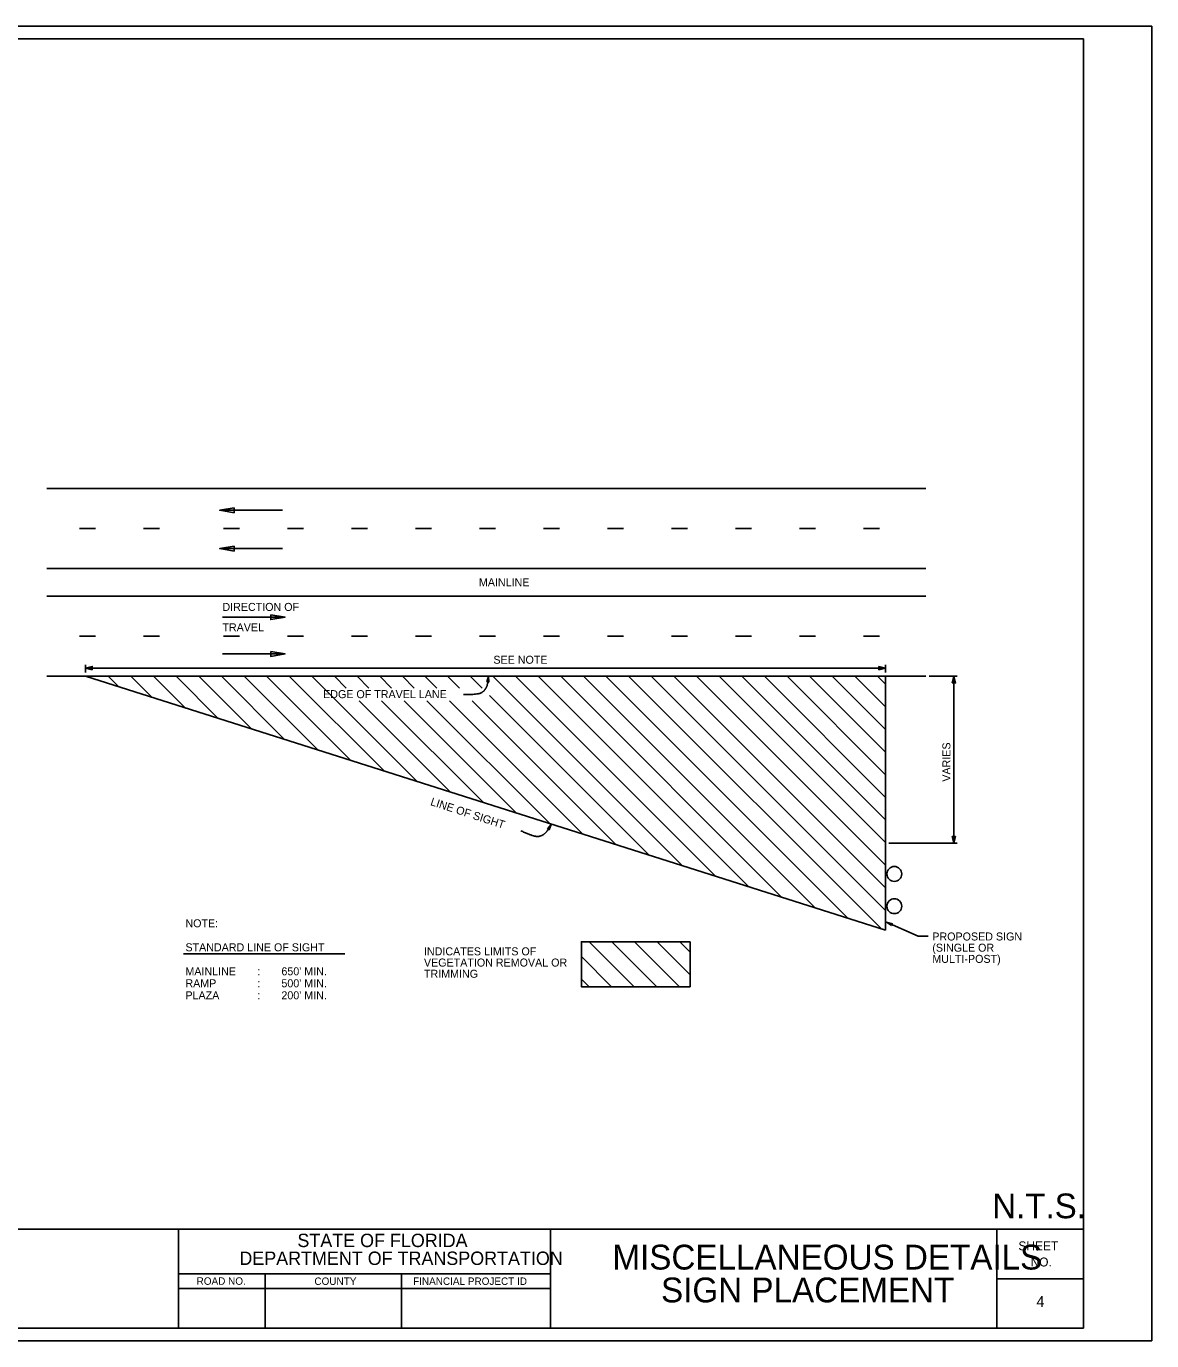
# Model space of a CAD drawing. Extents: x 17890189 to 17891344, y 17896595 to 17897992.
# Drawn here: x 17890708 to 17891344, y 17896595 to 17897337 of the extents above; entities that cross this region are included whole.
import ezdxf

# ---------------------------------------------------------------- set-up
doc = ezdxf.new("R2010")
doc.units = 0
for name, color, linetype in [('Default', 7, 'Continuous'), ('DimLines_dp', 7, 'Continuous'), ('LeaderLine_dp', 7, 'Continuous'), ('PlotBorder_dp', 7, 'Continuous'), ('ScratchEle_dp', 7, 'Continuous'), ('SheetBorder_dp', 7, 'Continuous'), ('SheetLines_dp', 7, 'Continuous'), ('TextLabel', 7, 'Continuous'), ('TextMisc', 7, 'Continuous'), ('TextShtNo', 7, 'Continuous')]:
    doc.layers.add(name, color=color, linetype=linetype)

msp = doc.modelspace()

# ---------------------------------------------------------------- linework, layer by layer
at = {"layer": 'Default'}
for p, q in [((17890719.8, 17897075.52), (17891216.02, 17897075.52)), ((17890738.25, 17897052.94), (17890747.28, 17897052.94)), ((17890774.38, 17897052.94), (17890783.41, 17897052.94)), ((17890819.54, 17897052.94), (17890828.57, 17897052.94)), ((17890855.67, 17897052.94), (17890864.7, 17897052.94)), ((17890891.8, 17897052.94), (17890900.83, 17897052.94)), ((17890927.93, 17897052.94), (17890936.96, 17897052.94)), ((17890964.06, 17897052.94), (17890973.09, 17897052.94)), ((17891000.19, 17897052.94), (17891009.22, 17897052.94)), ((17891036.32, 17897052.94), (17891045.35, 17897052.94)), ((17891072.44, 17897052.94), (17891081.48, 17897052.94)), ((17891108.57, 17897052.94), (17891117.61, 17897052.94)), ((17891144.7, 17897052.94), (17891153.73, 17897052.94)), ((17891180.83, 17897052.94), (17891189.86, 17897052.94)), ((17890719.8, 17897030.36), (17891216.02, 17897030.36)), ((17890719.8, 17897014.78), (17891216.02, 17897014.78)), ((17890738.25, 17896992.2), (17890747.28, 17896992.2)), ((17890774.38, 17896992.2), (17890783.41, 17896992.2)), ((17890819.54, 17896992.2), (17890828.57, 17896992.2)), ((17890855.67, 17896992.2), (17890864.7, 17896992.2)), ((17890891.8, 17896992.2), (17890900.83, 17896992.2)), ((17890927.93, 17896992.2), (17890936.96, 17896992.2)), ((17890964.06, 17896992.2), (17890973.09, 17896992.2)), ((17891000.19, 17896992.2), (17891009.22, 17896992.2)), ((17891036.32, 17896992.2), (17891045.35, 17896992.2)), ((17891072.44, 17896992.2), (17891081.48, 17896992.2)), ((17891108.57, 17896992.2), (17891117.61, 17896992.2)), ((17891144.7, 17896992.2), (17891153.73, 17896992.2)), ((17891180.83, 17896992.2), (17891189.86, 17896992.2)), ((17890741.72, 17896971.62), (17890741.72, 17896976.11)), ((17891193.33, 17896974.23), (17890741.72, 17896974.23)), ((17891193.33, 17896971.62), (17891193.33, 17896976.11)), ((17890719.8, 17896969.62), (17891216.02, 17896969.62)), ((17891193.33, 17896826.19), (17890741.72, 17896969.62)), ((17890741.75, 17896969.61), (17890741.74, 17896969.62)), ((17890760.47, 17896963.66), (17890754.51, 17896969.62)), ((17890779.19, 17896957.72), (17890767.29, 17896969.62)), ((17890797.9, 17896951.78), (17890780.06, 17896969.62)), ((17890816.62, 17896945.83), (17890792.84, 17896969.62)), ((17890835.34, 17896939.89), (17890805.61, 17896969.62)), ((17890854.06, 17896933.94), (17890818.38, 17896969.62)), ((17890872.78, 17896928), (17890831.16, 17896969.62)), ((17890891.49, 17896922.05), (17890843.93, 17896969.62)), ((17890910.21, 17896916.11), (17890856.7, 17896969.62)), ((17890928.93, 17896910.16), (17890869.48, 17896969.62)), ((17890888.92, 17896962.95), (17890882.25, 17896969.62)), ((17890901.69, 17896962.95), (17890895.02, 17896969.62)), ((17890914.47, 17896962.95), (17890907.8, 17896969.62)), ((17890927.24, 17896962.95), (17890920.57, 17896969.62)), ((17890940.01, 17896962.95), (17890933.34, 17896969.62)), ((17890952.79, 17896962.95), (17890946.12, 17896969.62)), ((17890965.56, 17896962.95), (17890958.89, 17896969.62)), ((17891078.68, 17896862.61), (17890971.66, 17896969.62)), ((17891097.4, 17896856.66), (17890984.44, 17896969.62)), ((17891116.11, 17896850.72), (17890997.21, 17896969.62)), ((17891134.83, 17896844.77), (17891009.98, 17896969.62)), ((17891153.55, 17896838.83), (17891022.76, 17896969.62)), ((17891172.27, 17896832.88), (17891035.53, 17896969.62)), ((17891190.99, 17896826.94), (17891048.3, 17896969.62)), ((17891193.33, 17896837.36), (17891061.08, 17896969.62)), ((17891193.33, 17896850.14), (17891073.85, 17896969.62)), ((17891193.33, 17896862.91), (17891086.63, 17896969.62)), ((17891193.33, 17896875.68), (17891099.4, 17896969.62)), ((17891193.33, 17896888.46), (17891112.17, 17896969.62)), ((17891193.33, 17896901.23), (17891124.95, 17896969.62)), ((17891193.33, 17896914), (17891137.72, 17896969.62)), ((17891193.33, 17896926.78), (17891150.49, 17896969.62)), ((17891193.33, 17896939.55), (17891163.27, 17896969.62)), ((17891193.33, 17896952.32), (17891176.04, 17896969.62)), ((17891193.33, 17896965.1), (17891188.81, 17896969.62)), ((17891193.33, 17896875.36), (17891193.33, 17896969.62)), ((17891217.91, 17896969.62), (17891233.8, 17896969.62)), ((17891059.96, 17896868.55), (17890969.73, 17896958.78)), ((17890947.65, 17896904.22), (17890896.09, 17896955.78)), ((17890966.37, 17896898.27), (17890908.86, 17896955.78)), ((17890985.09, 17896892.33), (17890921.64, 17896955.78)), ((17891003.8, 17896886.38), (17890934.41, 17896955.78)), ((17891022.52, 17896880.44), (17890947.18, 17896955.78)), ((17891041.24, 17896874.49), (17890959.96, 17896955.78)), ((17891193.33, 17896875.36), (17891193.33, 17896826.19)), ((17891051.51, 17896794.31), (17891026.09, 17896819.73)), ((17891064.28, 17896794.31), (17891038.86, 17896819.73)), ((17891077.06, 17896794.31), (17891051.64, 17896819.73)), ((17891083.02, 17896801.12), (17891064.41, 17896819.73)), ((17891083.02, 17896813.9), (17891077.18, 17896819.73)), ((17891038.73, 17896794.31), (17891021.68, 17896811.37)), ((17891025.96, 17896794.31), (17891021.68, 17896798.6))]:
    msp.add_line(p, q, dxfattribs=at)
for points in [[(17890745.48, 17896973.29), (17890741.72, 17896974.23), (17890745.48, 17896975.17)], [(17891189.57, 17896975.17), (17891193.33, 17896974.23), (17891189.57, 17896973.29)], [(17891002.46, 17896883.51), (17891003.38, 17896882.94), (17891004.62, 17896886)], [(17891083.02, 17896819.73), (17891021.68, 17896819.73), (17891021.68, 17896794.31), (17891083.02, 17896794.31)]]:
    msp.add_lwpolyline(points, close=True, dxfattribs=at)
for centre in [(17891198.32, 17896857.99), (17891198.32, 17896839.79)]:
    msp.add_circle(centre, 4.21, dxfattribs=at)
msp.add_open_spline([(17890987.39, 17896882.36), (17890995.04, 17896878.92), (17890999.26, 17896879.34), (17891002.68, 17896882.29), (17891004.52, 17896885.88)], degree=2, dxfattribs=at)
at = {"layer": 'DimLines_dp'}
msp.add_line((17891231.91, 17896969.62), (17891231.91, 17896875.36), dxfattribs=at)
at = {"layer": 'LeaderLine_dp'}
for p, q in [((17890852.86, 17897063.29), (17890817.45, 17897063.29)), ((17890852.86, 17897041.65), (17890817.45, 17897041.65)), ((17890818.97, 17897002.96), (17890854.38, 17897002.96)), ((17890818.97, 17896982.17), (17890854.38, 17896982.17)), ((17891195.22, 17896875.36), (17891233.8, 17896875.36)), ((17891211.78, 17896822.83), (17891193.93, 17896830.71)), ((17891217.5, 17896822.83), (17891211.78, 17896822.83))]:
    msp.add_line(p, q, dxfattribs=at)
for points in [[(17890825.58, 17897064.64), (17890825.58, 17897061.93), (17890817.45, 17897063.29)], [(17890825.58, 17897043.01), (17890825.58, 17897040.3), (17890817.45, 17897041.65)], [(17890846.25, 17897004.32), (17890846.25, 17897001.61), (17890854.38, 17897002.96)], [(17890846.25, 17896983.52), (17890846.25, 17896980.81), (17890854.38, 17896982.17)], [(17890968.27, 17896966.47), (17890969.34, 17896966.33), (17890969.22, 17896969.62)], [(17891230.97, 17896965.86), (17891231.91, 17896969.62), (17891232.86, 17896965.86)], [(17891232.86, 17896879.12), (17891231.91, 17896875.36), (17891230.97, 17896879.12)], [(17891196.68, 17896828.9), (17891197.12, 17896829.89), (17891193.93, 17896830.71)]]:
    msp.add_lwpolyline(points, close=True, dxfattribs=at)
msp.add_open_spline([(17890955, 17896959.24), (17890963.38, 17896959.24), (17890967.06, 17896961.36), (17890968.97, 17896965.45), (17890969.18, 17896969.47)], degree=2, dxfattribs=at)
at = {"layer": 'PlotBorder_dp'}
msp.add_lwpolyline([(17890188.62, 17896594.5), (17891343.62, 17896594.5), (17891343.62, 17897336.5), (17890188.62, 17897336.5)], close=True, dxfattribs=at)
at = {"layer": 'ScratchEle_dp'}
msp.add_line((17890796.99, 17896812.99), (17890888.02, 17896812.99), dxfattribs=at)
at = {"layer": 'SheetBorder_dp'}
for p, q in [((17890227.12, 17897329.5), (17891305.12, 17897329.5)), ((17891305.12, 17897329.5), (17891305.12, 17896601.5)), ((17890227.12, 17896657.5), (17891305.12, 17896657.5)), ((17890227.12, 17896601.5), (17891305.12, 17896601.5))]:
    msp.add_line(p, q, dxfattribs=at)
at = {"layer": 'SheetLines_dp'}
for p, q in [((17890794.12, 17896657.5), (17890794.12, 17896601.5)), ((17891004.12, 17896601.5), (17891004.12, 17896657.5)), ((17891256.12, 17896601.5), (17891256.12, 17896657.5)), ((17890794.12, 17896632.3), (17891004.12, 17896632.3)), ((17890843.12, 17896632.3), (17890843.12, 17896601.5)), ((17890920.12, 17896632.3), (17890920.12, 17896601.5)), ((17891256.12, 17896629.5), (17891305.12, 17896629.5)), ((17890794.12, 17896623.9), (17891004.12, 17896623.9))]:
    msp.add_line(p, q, dxfattribs=at)

# ---------------------------------------------------------------- texts
at = {"layer": 'Default'}
msp.add_text('N.T.S.', height=13.959, rotation=360, dxfattribs=at).set_placement((17891253.58, 17896663.64))
at = {"layer": 'TextLabel'}
for s, height, p in [('MAINLINE', 4.516, (17890963.78, 17897020.38)), ('DIRECTION OF', 4.5161, (17890818.97, 17897006.47)), ('TRAVEL', 4.516, (17890818.97, 17896994.95)), ('SEE NOTE', 4.516, (17890971.96, 17896976.65)), ('EDGE OF TRAVEL LANE', 4.5161, (17890875.84, 17896957.23)), ('NOTE:', 4.516, (17890798.09, 17896827.88)), ('PROPOSED SIGN', 4.5161, (17891219.76, 17896820.43)), ('STANDARD LINE OF SIGHT', 4.5161, (17890798.09, 17896814.33)), ('(SINGLE OR', 4.516, (17891219.76, 17896814.11)), ('VEGETATION REMOVAL OR', 4.5161, (17890932.76, 17896805.72)), ('INDICATES LIMITS OF', 4.5161, (17890932.76, 17896812.05)), ('MULTI-POST)', 4.5161, (17891219.76, 17896807.79)), ('MAINLINE', 4.516, (17890798.09, 17896800.78)), (':', 4.52, (17890838.73, 17896800.78)), ("650' MIN.", 4.516, (17890852.28, 17896800.78)), ('TRIMMING', 4.516, (17890932.76, 17896799.4)), ('RAMP', 4.516, (17890798.09, 17896794.01)), (':', 4.52, (17890838.73, 17896794.01)), ("500' MIN.", 4.516, (17890852.28, 17896794.01)), ('PLAZA', 4.516, (17890798.09, 17896787.23)), (':', 4.52, (17890838.73, 17896787.23)), ("200' MIN.", 4.516, (17890852.28, 17896787.23))]:
    msp.add_text(s, height=height, dxfattribs=at).set_placement(p)
for s, height, rotation, p in [('VARIES', 4.516, 90, (17891229.97, 17896910.08)), ('LINE OF SIGHT', 4.5161, 341.99999, (17890936.07, 17896896.94))]:
    msp.add_text(s, height=height, rotation=rotation, dxfattribs=at).set_placement(p)
at = {"layer": 'TextMisc'}
for s, height, p in [('STATE OF FLORIDA', 7.56, (17890861.32, 17896647.35)), ('MISCELLANEOUS DETAILS', 14.0171, (17891039.14, 17896634.68)), ('DEPARTMENT OF TRANSPORTATION', 7.56, (17890828.56, 17896637.27)), ('ROAD NO.', 4.2, (17890804.41, 17896626.07)), ('COUNTY', 4.2, (17890870.91, 17896626)), ('FINANCIAL PROJECT ID', 4.2, (17890926.63, 17896626)), ('SIGN PLACEMENT', 14.0171, (17891066.6, 17896616.14))]:
    msp.add_text(s, height=height, dxfattribs=at).set_placement(p)
for s, p in [('SHEET', (17891268.37, 17896645.53)), ('NO.', (17891275.23, 17896636.43))]:
    msp.add_text(s, height=5.04, rotation=359.86066, dxfattribs=at).set_placement(p)
at = {"layer": 'TextShtNo'}
msp.add_text('4', height=6.17, dxfattribs=at).set_placement((17891278.53, 17896613.56))

doc.saveas('drawing.dxf')
